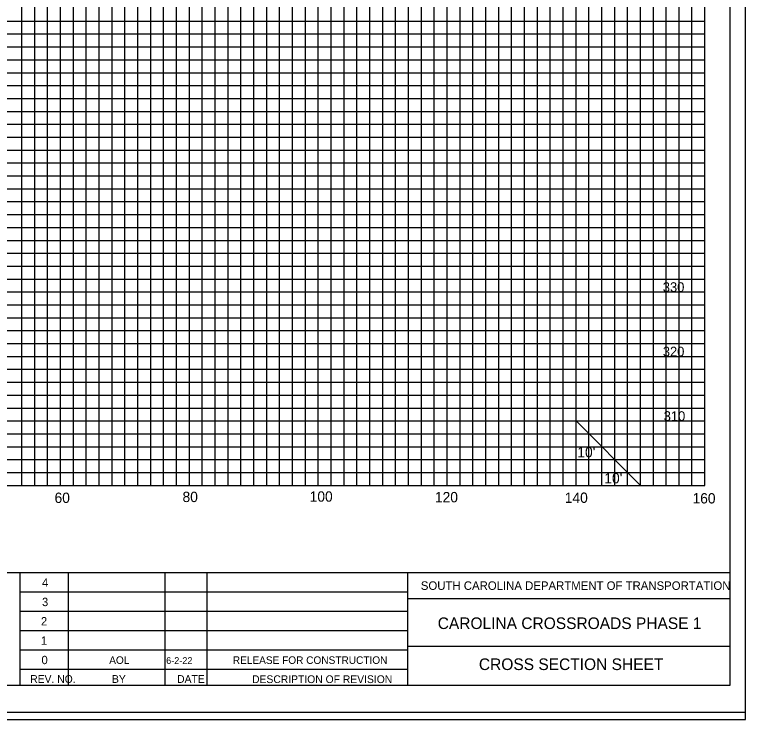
# Model space of a CAD drawing. Extents: x 967 to 1746, y 964 to 7904.
# Drawn here: x 1632.9 to 1746.3, y 1803.7 to 1913 of the extents above; entities that cross this region are included whole.
import ezdxf

# ---------------------------------------------------------------- set-up
doc = ezdxf.new("R2010")
doc.units = 0
for name, color, linetype in [('Default', 7, 'Continuous'), ('RD_SHT_Bndy', 7, 'Continuous'), ('RD_SHT_IplotShp', 7, 'Continuous'), ('RD_SHT_Misc1', 7, 'Continuous'), ('RD_SHT_MjGrid', 7, 'Continuous'), ('RD_SHT_MnGrid', 7, 'Continuous'), ('RD_SHT_TX', 7, 'Continuous'), ('RD_Sketch1', 7, 'Continuous')]:
    doc.layers.add(name, color=color, linetype=linetype)

msp = doc.modelspace()

# ---------------------------------------------------------------- linework, layer by layer
at = {"layer": 'RD_SHT_Bndy'}
for p, q in [((1743.89, 2018.46), (1743.89, 1808.98)), ((1416.11, 1826.49), (1743.89, 1826.49)), ((1633.76, 1808.94), (1633.76, 1826.49)), ((1641.26, 1808.95), (1641.26, 1826.48)), ((1656.26, 1808.95), (1656.26, 1826.48)), ((1662.76, 1808.95), (1662.76, 1826.48)), ((1693.88, 1808.98), (1693.88, 1826.49)), ((1633.76, 1823.48), (1693.88, 1823.48)), ((1743.93, 1822.43), (1693.88, 1822.43)), ((1633.76, 1820.48), (1693.88, 1820.48)), ((1633.76, 1817.48), (1693.88, 1817.48)), ((1633.76, 1814.48), (1693.88, 1814.48)), ((1743.89, 1815.04), (1693.88, 1815.04)), ((1633.76, 1811.48), (1693.88, 1811.48)), ((1743.89, 1808.98), (1416.11, 1808.98))]:
    msp.add_line(p, q, dxfattribs=at)
at = {"layer": 'RD_SHT_IplotShp'}
for points in [[(1387.41, 1803.72), (1746.28, 1803.72), (1746.28, 2023.72), (1387.41, 2023.72)], [(1408.52, 1804.84), (1746.28, 1804.84), (1746.28, 2022.6), (1408.52, 2022.6)]]:
    msp.add_lwpolyline(points, close=True, dxfattribs=at)
at = {"layer": 'RD_SHT_MjGrid'}
for p, q in [((1640, 1840), (1640, 2010)), ((1650, 1840), (1650, 2010)), ((1660, 1840), (1660, 2010)), ((1670, 1840), (1670, 2010)), ((1680, 1840), (1680, 2010)), ((1690, 1840), (1690, 2010)), ((1700, 1840), (1700, 2010)), ((1710, 1840), (1710, 2010)), ((1720, 1840), (1720, 2010)), ((1730, 1840), (1730, 2010)), ((1740, 1840), (1740, 2010)), ((1420, 1910), (1740, 1910)), ((1420, 1900), (1740, 1900)), ((1420, 1890), (1740, 1890)), ((1420, 1880), (1740, 1880)), ((1420, 1870), (1740, 1870)), ((1420, 1860), (1740, 1860)), ((1420, 1850), (1740, 1850)), ((1420, 1840), (1740, 1840))]:
    msp.add_line(p, q, dxfattribs=at)
at = {"layer": 'RD_SHT_MnGrid'}
for p, q in [((1634, 1840), (1634, 2010)), ((1636, 1840), (1636, 2010)), ((1638, 1840), (1638, 2010)), ((1642, 1840), (1642, 2010)), ((1644, 1840), (1644, 2010)), ((1646, 1840), (1646, 2010)), ((1648, 1840), (1648, 2010)), ((1652, 1840), (1652, 2010)), ((1654, 1840), (1654, 2010)), ((1656, 1840), (1656, 2010)), ((1658, 1840), (1658, 2010)), ((1662, 1840), (1662, 2010)), ((1664, 1840), (1664, 2010)), ((1666, 1840), (1666, 2010)), ((1668, 1840), (1668, 2010)), ((1672, 1840), (1672, 2010)), ((1674, 1840), (1674, 2010)), ((1676, 1840), (1676, 2010)), ((1678, 1840), (1678, 2010)), ((1682, 1840), (1682, 2010)), ((1684, 1840), (1684, 2010)), ((1686, 1840), (1686, 2010)), ((1688, 1840), (1688, 2010)), ((1692, 1840), (1692, 2010)), ((1694, 1840), (1694, 2010)), ((1696, 1840), (1696, 2010)), ((1698, 1840), (1698, 2010)), ((1702, 1840), (1702, 2010)), ((1704, 1840), (1704, 2010)), ((1706, 1840), (1706, 2010)), ((1708, 1840), (1708, 2010)), ((1712, 1840), (1712, 2010)), ((1714, 1840), (1714, 2010)), ((1716, 1840), (1716, 2010)), ((1718, 1840), (1718, 2010)), ((1722, 1840), (1722, 2010)), ((1724, 1840), (1724, 2010)), ((1726, 1840), (1726, 2010)), ((1728, 1840), (1728, 2010)), ((1732, 1840), (1732, 2010)), ((1734, 1840), (1734, 2010)), ((1736, 1840), (1736, 2010)), ((1738, 1840), (1738, 2010)), ((1420, 1912), (1740, 1912)), ((1420, 1908), (1740, 1908)), ((1420, 1906), (1740, 1906)), ((1420, 1904), (1740, 1904)), ((1420, 1902), (1740, 1902)), ((1420, 1898), (1740, 1898)), ((1420, 1896), (1740, 1896)), ((1420, 1894), (1740, 1894)), ((1420, 1892), (1740, 1892)), ((1420, 1888), (1740, 1888)), ((1420, 1886), (1740, 1886)), ((1420, 1884), (1740, 1884)), ((1420, 1882), (1740, 1882)), ((1420, 1878), (1740, 1878)), ((1420, 1876), (1740, 1876)), ((1420, 1874), (1740, 1874)), ((1420, 1872), (1740, 1872)), ((1420, 1868), (1740, 1868)), ((1420, 1866), (1740, 1866)), ((1420, 1864), (1740, 1864)), ((1420, 1862), (1740, 1862)), ((1420, 1858), (1740, 1858)), ((1420, 1856), (1740, 1856)), ((1420, 1854), (1740, 1854)), ((1420, 1852), (1740, 1852)), ((1420, 1848), (1740, 1848)), ((1420, 1846), (1740, 1846)), ((1420, 1844), (1740, 1844)), ((1420, 1842), (1740, 1842))]:
    msp.add_line(p, q, dxfattribs=at)
at = {"layer": 'RD_SHT_TX'}
msp.add_line((1720, 1850), (1730, 1840), dxfattribs=at)
at = {"layer": 'RD_Sketch1'}
msp.add_lwpolyline([(1387.41, 1803.72), (1746.28, 1803.72), (1746.28, 2023.72), (1387.41, 2023.72)], close=True, dxfattribs=at)

# ---------------------------------------------------------------- texts
at = {"layer": 'Default'}
for s, p in [('330', (1733.47, 1870)), ('320', (1733.47, 1860)), ('310', (1733.61, 1850))]:
    msp.add_text(s, height=1.5, dxfattribs=at).set_placement(p)
at = {"layer": 'RD_SHT_Misc1'}
for s, height, p in [('AOL', 1.17, (1647.56, 1812.32)), ('6-2-22', 1.053, (1656.4, 1812.31)), ('RELEASE FOR CONSTRUCTION', 1.17, (1666.74, 1812.32))]:
    msp.add_text(s, height=height, dxfattribs=at).set_placement(p)
at = {"layer": 'RD_SHT_TX'}
for s, height, p in [("10'", 1.6, (1720.21, 1844.36)), ("10'", 1.6, (1724.4, 1840.32)), ('60', 1.6, (1639.08, 1837.28)), ('80', 1.6, (1658.94, 1837.42)), ('100', 1.6, (1678.67, 1837.48)), ('120', 1.6, (1698.11, 1837.38)), ('140', 1.6, (1718.26, 1837.29)), ('160', 1.6, (1738.08, 1837.2)), ('4', 1.3, (1637.13, 1824.28)), ('SOUTH CAROLINA DEPARTMENT OF TRANSPORTATION', 1.32, (1695.92, 1823.8)), ('3', 1.3, (1637.13, 1821.28)), ('2', 1.3, (1636.97, 1818.28)), ('1', 1.3, (1636.97, 1815.28)), ('0', 1.3, (1637.05, 1812.28)), ('REV. NO.', 1.2, (1635.3, 1809.38)), ('BY', 1.2, (1647.99, 1809.38)), ('DATE', 1.2, (1658.1, 1809.38)), ('DESCRIPTION OF REVISION', 1.2, (1669.73, 1809.35))]:
    msp.add_text(s, height=height, dxfattribs=at).set_placement(p)
for s, p in [('CAROLINA CROSSROADS PHASE 1', (1698.54, 1817.73)), ('CROSS SECTION SHEET', (1704.93, 1811.37))]:
    msp.add_text(s, height=1.8, rotation=0, dxfattribs=at).set_placement(p)

doc.saveas('drawing.dxf')
